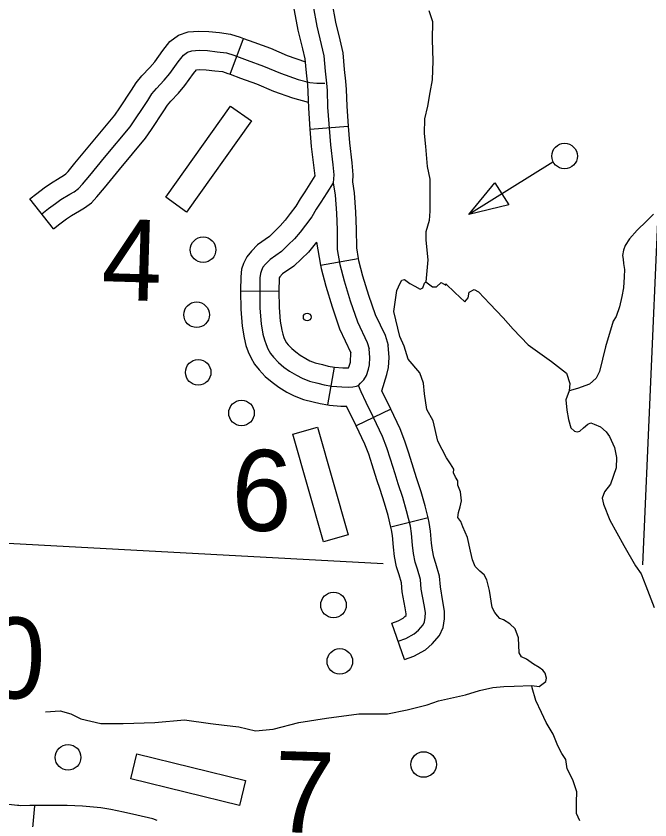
# Model space of a CAD drawing. Extents: x 653372 to 905732, y 627442 to 787275.
# Drawn here: x 702723 to 705201, y 746022 to 749166 of the extents above; entities that cross this region are included whole.
import ezdxf

# ---------------------------------------------------------------- set-up
doc = ezdxf.new("R2010")
doc.units = 0
for name, color, linetype in [('32', 7, 'Continuous'), ('35', 7, 'Continuous'), ('45', 7, 'Continuous'), ('5', 7, 'Continuous'), ('56', 7, 'Continuous'), ('9', 7, 'Continuous')]:
    doc.layers.add(name, color=color, linetype=linetype)

msp = doc.modelspace()

# ---------------------------------------------------------------- linework, layer by layer
at = {"layer": '32'}
for p, q in [((703871.8, 748724.6), (704021.3, 748735.9)), ((703913.2, 748192.1), (704061, 748217.5)), ((703600.7, 748091), (703750.7, 748091.9)), ((703941.3, 747645.3), (703968.1, 747792.9)), ((704187.9, 747628.8), (704052.7, 747563.9)), ((704333.8, 747203.5), (704188.2, 747167.4)), ((704241.6, 746650.1), (704191.4, 746791.5)), ((702795.1, 746077.3), (702781.5, 745927.9))]:
    msp.add_line(p, q, dxfattribs=at)
for points in [[(703944.9, 749269.6), (703957.3, 749220.8), (703971.6, 749142.7), (703989.2, 749072.9), (704000.7, 749022.4), (704006.2, 748958), (704011.1, 748911.3), (704013.9, 748878.8), (704015.5, 748813.7), (704021.3, 748735.9)], [(703799.5, 749232.9), (703810.6, 749188.9), (703825, 749110.8), (703843.3, 749037.9), (703852.1, 748999.3), (703856.9, 748943.8), (703861.8, 748896.9), (703864.1, 748870.6), (703865.6, 748806.3), (703871.8, 748724.6)], [(703883.9, 749204.8), (703898.3, 749126.7), (703916.3, 749055.4), (703926.4, 749010.8), (703931.5, 748950.9), (703936.4, 748904.1), (703939, 748874.7), (703940.5, 748810), (703951.6, 748663), (703960.8, 748584.5), (703964.8, 748545.3), (703962.2, 748514.6)], [(704021.3, 748735.9), (704026.3, 748670.2), (704035.3, 748592.6), (704040.1, 748545.9), (704037.7, 748517.5), (704044.6, 748475), (704050.4, 748399.2), (704052.8, 748332.5), (704053.8, 748259.8), (704061, 748217.5)], [(703871.8, 748724.6), (703877, 748655.8), (703890.3, 748541.2)], [(703890.3, 748541.2), (703851.6, 748478.8), (703833, 748451), (703816.7, 748423.4), (703794.9, 748394.4), (703774.4, 748367.7), (703755.9, 748345.4), (703735.2, 748325.2), (703713.1, 748304.4), (703666.3, 748271.4), (703642.8, 748246.4), (703624.6, 748225.1), (703612.3, 748198.9), (703604.4, 748176), (703601.4, 748146.9), (703600.7, 748092.9), (703600.7, 748090.9)], [(703962.2, 748514.6), (703937.3, 748474.7), (703914.7, 748438.2), (703896.6, 748411.1), (703879.2, 748381.6), (703854.5, 748349), (703833, 748320.9), (703811.1, 748294.5), (703787.1, 748271.1), (703760.6, 748246.1), (703715.7, 748214.5), (703698.7, 748196.4), (703688.2, 748184), (703681.9, 748170.7), (703678.2, 748159.8), (703676.4, 748142.5), (703675.7, 748092.7), (703676.2, 748023.4), (703681.1, 747963.2), (703688, 747922.8), (703693.6, 747899.8), (703700.2, 747881.4), (703707.7, 747864.3), (703717.8, 747846.6), (703729.6, 747831.9), (703748.8, 747811), (703770.3, 747793.5), (703791.8, 747777.6), (703818.7, 747761.2), (703840.8, 747749.9), (703869.6, 747738.5), (703902.5, 747730.3), (703927.2, 747724.1), (703957.9, 747718.5), (703997.1, 747715.7), (704024.1, 747714.9), (704039.4, 747715.7), (704053.4, 747718.2), (704061.1, 747721), (704069.4, 747730.4), (704082, 747743.5), (704093.1, 747761), (704100.6, 747784.8), (704104.9, 747802.5), (704106.2, 747830.3), (704103.8, 747865)], [(703962.2, 748514.6), (703970, 748466.2), (703975.5, 748395), (703977.8, 748330.7), (703978.8, 748252.9), (703988.9, 748194.2), (704005.6, 748130.3), (704029.4, 748051.9), (704057.4, 747970.7), (704095.6, 747890.1), (704103.8, 747865)], [(703897.8, 748281.5), (703866.3, 748243.5), (703839.1, 748217), (703808.2, 748187.9), (703765.1, 748157.6), (703754.6, 748146.4), (703751.8, 748143.1), (703751.3, 748138.2), (703750.7, 748092.5), (703750.7, 748091.9)], [(703897.8, 748281.5), (703913.2, 748192.1)], [(704061, 748217.5), (704062.3, 748210.1), (704077.8, 748150.7), (704100.8, 748075), (704127, 747999.1), (704165.3, 747918), (704178, 747879.6)], [(703913.2, 748192.1), (703915.5, 748178.4), (703933.4, 748110), (703958.1, 748028.7), (703987.9, 747942.4), (704032, 747849.2)], [(703600.7, 748091), (703601.2, 748020), (703606.7, 747953.9), (703614.5, 747907.6), (703621.7, 747878), (703630.5, 747853.6), (703640.6, 747830.6), (703655.5, 747804.3), (703672.7, 747783), (703697.2, 747756.3), (703724.2, 747734.3), (703749.9, 747715.3), (703782.1, 747695.6), (703809.9, 747681.5), (703846.6, 747666.9), (703884.3, 747657.6), (703911.3, 747650.8), (703941.3, 747645.3)], [(703750.7, 748091.9), (703751.2, 748026.7), (703755.6, 747972.5), (703761.4, 747938), (703765.5, 747921.5), (703769.9, 747909.2), (703774.9, 747898), (703780, 747888.9), (703786.5, 747880.8), (703800.4, 747865.7), (703816.3, 747852.7), (703833.6, 747839.9), (703855.3, 747826.7), (703871.7, 747818.4), (703892.6, 747810.1), (703920.7, 747803.1), (703943.1, 747797.4), (703968.1, 747792.9)], [(703967.4, 747793), (704001, 747790.6), (704022.6, 747789.9), (704022.8, 747790.1), (704024.5, 747792.9), (704028.3, 747805), (704030.3, 747813.2), (704032, 747849.2)], [(704152.7, 747700.4), (704172.9, 747764.7), (704179.5, 747791.7), (704181.3, 747831.1), (704178, 747879.6)], [(704216.5, 746720.8), (704247.3, 746731.7), (704279.9, 746749.3), (704296.4, 746764), (704314.8, 746784.6), (704320.2, 746796.3), (704322.4, 746814), (704323, 746833.4), (704318, 746864), (704307.1, 746924.3), (704304.1, 746962.5), (704292.6, 747003.4), (704283.3, 747030.7), (704276.7, 747064.7), (704272.6, 747097), (704268.9, 747142.7), (704264.7, 747170.8), (704249.6, 747231.5), (704235.1, 747283.5), (704217.3, 747337.3), (704204.9, 747375.7), (704186.4, 747433.7), (704172.5, 747478.1), (704155.2, 747521.7), (704120.3, 747596.3), (704091.6, 747654.7), (704072.2, 747697), (704061.1, 747721)], [(704333.8, 747203.5), (704322.1, 747250.6), (704306.9, 747305.4), (704288.6, 747360.6), (704276.3, 747398.6), (704257.9, 747456.3), (704243.3, 747503.1), (704224.1, 747551.5), (704187.9, 747628.8), (704152.7, 747700.4)], [(703941.3, 747645.3), (703948.4, 747644), (703993.2, 747640.7), (704015.2, 747640.1)], [(704188.2, 747167.4), (704177.1, 747212.4), (704163.3, 747261.6), (704146, 747314), (704133.5, 747352.8), (704114.9, 747411.1), (704101.8, 747453.1), (704086.3, 747492), (704052.7, 747563.9), (704015.2, 747640.1)], [(704241.6, 746650.1), (704277.8, 746663), (704323.3, 746687.5), (704349.5, 746710.9), (704378.1, 746743), (704393.2, 746775.3), (704397.3, 746808.2), (704398.2, 746838.4), (704391.9, 746876.7), (704381.6, 746934), (704378.2, 746975.7), (704364.3, 747025.6), (704355.9, 747050), (704350.8, 747076.6), (704347.2, 747104.7), (704343.5, 747151.4), (704338.3, 747185.4), (704333.8, 747203.5)], [(704191.4, 746791.5), (704216.7, 746800.5), (704236.5, 746811.1), (704243.3, 746817.2), (704247.6, 746822), (704247.8, 746828.4), (704244.1, 746851.3), (704232.7, 746914.6), (704229.9, 746949.2), (704221, 746981.2), (704210.6, 747011.4), (704202.6, 747052.9), (704198, 747089.2), (704194.4, 747134.1), (704191, 747156.1), (704188.2, 747167.4)], [(702734.4, 746078.3), (702728.7, 746078.8), (702704.7, 746080.4), (702690.1, 746082.9), (702682.1, 746084.5), (702675.5, 746086.3), (702659.4, 746093), (702619.4, 746099.4), (702528.9, 746109.7), (702455.7, 746123.9), (702376, 746139.6), (702292.5, 746156.5), (702224, 746170.6)], [(703274.5, 746020.3), (703258.2, 746025.9), (703194.8, 746040.9), (703142.5, 746052.5), (703093.7, 746062.8), (703054.2, 746069.3), (702982.5, 746075.9), (702923, 746078.2), (702831.9, 746079), (702777.2, 746077.8), (702741.5, 746077.6), (702734.4, 746078.3)]]:
    msp.add_lwpolyline(points, dxfattribs=at)
at = {"layer": '35'}
for points in [[(704337.2, 749188.6), (704350.7, 749145.5), (704350, 749073.8), (704352.1, 748991.5), (704349.8, 748916.9), (704340.9, 748867.8), (704331.8, 748814.3), (704319.9, 748765), (704318.1, 748706.8), (704324, 748655.8), (704330.7, 748578.2), (704339.9, 748528.5), (704340.6, 748403.2), (704337.8, 748367.2), (704324.5, 748322.8), (704325, 748289.9), (704333.2, 748213.4), (704324.8, 748126.6)], [(705215.2, 748391.1), (705187.8, 748363.6), (705151.4, 748328.4), (705121.2, 748295.7), (705104.8, 748268.6), (705098, 748250.7), (705093.8, 748229.6), (705096.1, 748215.8), (705097.4, 748198.9), (705102, 748174.9), (705100.3, 748146.7), (705098.1, 748103.3), (705090.8, 748068.9), (705081.7, 748028.6), (705069, 747990.8), (705057.9, 747972.6), (705027.4, 747872.6), (705004.2, 747775.9), (704991, 747749.8), (704964.6, 747726.6), (704917.2, 747709.5), (704884.6, 747700.3)], [(702838.2, 746444.3), (702895.7, 746448.9), (702937.5, 746437.1), (702976.3, 746417.5), (703054.7, 746399.4), (703141.5, 746399.4), (703265.3, 746403.6), (703381.3, 746413.3), (703483.5, 746399.7), (703535.9, 746392.8), (703593.6, 746385.8), (703658.9, 746370.7), (703727.5, 746376.6), (703828.3, 746402.5), (703936.7, 746420.3), (704063.5, 746437.5), (704175.2, 746436.8), (704252, 746452.9), (704330.2, 746472.3), (704374.1, 746488.1), (704480, 746511.9), (704534.5, 746528.5), (704587.4, 746539.6), (704629.6, 746543.6), (704670.5, 746545.2), (704739, 746547.4)]]:
    msp.add_lwpolyline(points, dxfattribs=at)
at = {"layer": '45'}
for p, q in [((703560.2, 748938.8), (703612.5, 749079.3)), ((702869.4, 748333.9), (702776.9, 748451.9))]:
    msp.add_line(p, q, dxfattribs=at)
for points in [[(703128, 748807.1), (703174.8, 748876.8), (703192.7, 748905.5), (703215.1, 748932.9), (703246.3, 748965.7), (703265.3, 748987.8), (703296.7, 749031.5), (703324.2, 749067.5), (703357.5, 749091.9), (703395.8, 749105.1), (703437.5, 749107.7), (703477.2, 749106.5), (703517.6, 749101.6), (703561.7, 749096.2), (703599.4, 749084.2), (703612.5, 749079.3)], [(703612.5, 749079.3), (703652.6, 749064.4), (703717.8, 749040.7), (703783.2, 749012.8), (703854.7, 748988.1)], [(702823.1, 748392.9), (702849.1, 748413.3), (702876.7, 748433.6), (702898.3, 748449), (702932.8, 748469.9), (702950, 748479.5), (702967.3, 748492.6), (702983, 748509), (703011, 748542.8), (703068.9, 748613.8), (703168.8, 748733.3), (703237.8, 748836.1), (703253.8, 748861.8), (703271.4, 748883.3), (703301.9, 748915.3), (703324.3, 748941.4), (703357, 748986.9), (703377.2, 749013.3), (703392.7, 749024.7), (703410.7, 749030.9), (703438.6, 749032.6), (703471.5, 749031.6), (703508.6, 749027.1), (703545.6, 749022.6), (703574.9, 749013.3), (703626.7, 748994), (703690.3, 748970.9), (703756.2, 748942.8), (703826, 748918.7), (703871.3, 748906.3), (703899.1, 748903.8), (703930.4, 748904.6)], [(703252.5, 748723.4), (703300.8, 748795.4), (703315, 748818.1), (703327.6, 748833.6), (703357.5, 748865), (703383.3, 748895), (703417.2, 748942.2), (703428.4, 748956.8), (703439.8, 748957.5), (703465.9, 748956.8), (703499.6, 748952.7), (703529.6, 748949), (703550.4, 748942.4), (703560.2, 748938.8)], [(703560.2, 748938.8), (703600.9, 748923.6), (703662.7, 748901.2), (703729.2, 748872.7), (703803.9, 748847), (703865, 748830.3)], [(702776.9, 748451.9), (702803.8, 748473), (702832.8, 748494.3), (702857, 748511.6), (702894.9, 748534.7), (702908.9, 748542.5), (702917.3, 748548.8), (702926.9, 748558.9), (702953.1, 748590.5), (703011.1, 748661.5), (703108.8, 748778.4), (703128, 748807.1)], [(702869.4, 748333.9), (702894.4, 748353.5), (702920.7, 748372.8), (702939.7, 748386.3), (702970.6, 748405.1), (702991, 748416.6), (703017.2, 748436.3), (703039, 748459.1), (703068.9, 748495.2), (703126.7, 748566), (703228.9, 748688.3), (703252.5, 748723.4)]]:
    msp.add_lwpolyline(points, dxfattribs=at)
at = {"layer": '5'}
for points in [[(705232.1, 748392), (705171.7, 747020.4)], [(704158.3, 747023.6), (702448.7, 747116.1)]]:
    msp.add_lwpolyline(points, dxfattribs=at)
at = {"layer": '56'}
for p, q in [((704492.4, 748389.8), (704595.1, 748514.2)), ((704595.1, 748514.2), (704649.2, 748427.7)), ((704649.2, 748427.7), (704492.4, 748389.8))]:
    msp.add_line(p, q, dxfattribs=at)
for points in [[(703561.9, 748814.4), (703643.4, 748756.4), (703389.6, 748400), (703308.1, 748458)], [(703805.1, 747531.2), (703901.3, 747558.6), (704020.8, 747137.7), (703924.6, 747110.4)], [(703171.2, 746183.2), (703195, 746280.3), (703619.9, 746176.1), (703596.1, 746079)]]:
    msp.add_lwpolyline(points, close=True, dxfattribs=at)
msp.add_lwpolyline([(704820.8, 748595.2), (704492.4, 748389.8)], dxfattribs=at)
for centre, radius in [((704867.3, 748618.9), 50), ((703454.2, 748252.5), 50), ((703428.7, 747998.1), 50), ((703861, 747989.2), 15), ((703435, 747772.8), 50), ((703604.2, 747613.7), 50), ((703964, 746862.6), 50), ((703988.7, 746642), 50), ((702926.3, 746266.7), 50), ((704316.3, 746238.7), 50)]:
    msp.add_circle(centre, radius, dxfattribs=at)
at = {"layer": '9'}
for points in [[(704461.9, 747189.8), (704450.5, 747204.6), (704452.4, 747224.2), (704459.7, 747246.3), (704464.3, 747269.8), (704460.1, 747305.3), (704450.4, 747331.8), (704449.6, 747348.9), (704440.8, 747362.3), (704433.5, 747379.6), (704433.9, 747394), (704421.5, 747415.4), (704405.1, 747438.1), (704371.6, 747503.4), (704353, 747582.7), (704328.2, 747628), (704319.5, 747688.6), (704315.5, 747730.7), (704301, 747770.5), (704255.4, 747824.3), (704240.2, 747874.7), (704223.8, 747913.4), (704200.2, 748010.9), (704211, 748093.3), (704225, 748121.7), (704230.6, 748133.4), (704241.4, 748136.2), (704261.7, 748120.6), (704282.3, 748109.5), (704303, 748098.4), (704313.6, 748103.3), (704319.4, 748121.5), (704324.8, 748126.6), (704335, 748118.4), (704350.4, 748107.5), (704366.2, 748107), (704385.1, 748124.8), (704402.9, 748114.4), (704403.2, 748119), (704438.7, 748084.5), (704477.2, 748048.6), (704490.8, 748063.9), (704494, 748086.1), (704514.1, 748097.3), (704530.8, 748087.6), (704575.3, 748040.4), (704627.4, 747986.3)], [(704627.4, 747986.3), (704666.7, 747942), (704724.7, 747880.4), (704816.8, 747814.9), (704875.2, 747769), (704888.3, 747728.7), (704884.6, 747700.3), (704872.1, 747665), (704876.6, 747625), (704882.6, 747587.7), (704891.6, 747556.1), (704905.5, 747542.9), (704916.8, 747539.7), (704926.8, 747542.2), (704941.5, 747556), (704957.6, 747569.8), (704970.6, 747575.1), (704983.2, 747570.5), (705007.1, 747559.8), (705029.4, 747540.6), (705043, 747521.6), (705063.1, 747478.3), (705070.5, 747439.6), (705069.3, 747399.7), (705047.4, 747334.8), (705023.7, 747305.6), (705014.4, 747280.2), (705019.4, 747257.2), (705044.6, 747195.2), (705098.6, 747095.2), (705144.7, 747015.5), (705166.5, 746984.9), (705185.1, 746937.7), (705218.1, 746852.7)], [(704926.3, 746018.4), (704914.1, 746047.6), (704914.1, 746090.9), (704915.3, 746131.6), (704899.7, 746179.2), (704877.4, 746221.9), (704871.9, 746258.8), (704856.9, 746281.5), (704840.7, 746312.2), (704822.4, 746357.3), (704794.9, 746402.8), (704776.5, 746442.7), (704754.3, 746489.3), (704740, 746538.2), (704739, 746547.4), (704767.7, 746543.9), (704794.5, 746564.1), (704796.2, 746575.9), (704791.6, 746595.7), (704782.7, 746607.8), (704768.6, 746618.7), (704745.4, 746631.2), (704718.5, 746650.4), (704699.1, 746660.1), (704690.4, 746676.1), (704686.9, 746734.8), (704673.5, 746769.3), (704653.1, 746789.6), (704628.7, 746804.8), (704614.4, 746810.5), (704605.5, 746819.9), (704594.1, 746833.4), (704584.2, 746853.4), (704574.4, 746919.2), (704563.9, 746961.5), (704552.6, 746980.2), (704536, 746995.2), (704518.2, 747012.7), (704507.2, 747039.3), (704499.1, 747073.7), (704487.6, 747127.4), (704469.1, 747168.6), (704461.9, 747189.8)]]:
    msp.add_lwpolyline(points, dxfattribs=at)

# ---------------------------------------------------------------- texts
at = {"layer": '56'}
for s, p in [('4', (703054.4, 748057.9)), ('6', (703561.2, 747156.3)), ('10', (702361.2, 746507.8)), ('7', (703727.4, 745975.4))]:
    msp.add_text(s, height=316.8, rotation=358.28, dxfattribs=at).set_placement(p)

doc.saveas('drawing.dxf')
